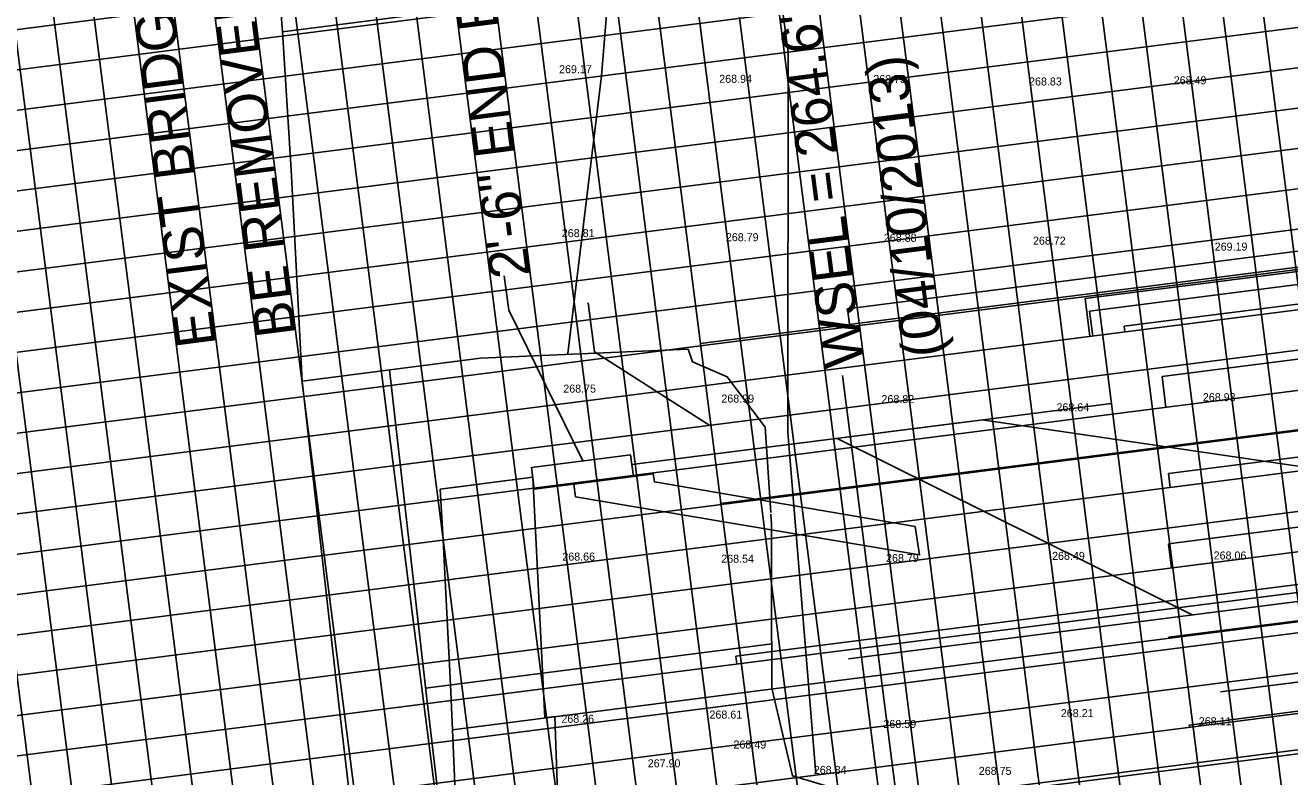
# Model space of a CAD drawing. Extents: x 2166991 to 2168450, y 842134 to 844444.
# Drawn here: x 2167712.5 to 2167870.5, y 843413.8 to 843507.6 of the extents above; entities that cross this region are included whole.
import ezdxf

# ---------------------------------------------------------------- set-up
doc = ezdxf.new("R2010")
doc.units = 0
for name, color, linetype in [('Exist Hydrographic Top of Bank', 7, 'Continuous'), ('Exist Plan Preparation Drainage Notes Label', 7, 'Continuous'), ('Prop Boundary Buffer Zone 1', 7, 'Continuous'), ('Prop Boundary Buffer Zone 2', 7, 'Continuous'), ('Prop Drainage Structure Bridge', 7, 'Continuous'), ('Prop Drainage Structure Drop Inlet Grate 2 Narrow Slots and Flat Grates 840 29 CELL', 7, 'Continuous'), ('Prop Drainage Structure Drop Inlet Grate 2 Wide Slots and Flat Grates 840 20 TB Label', 7, 'Continuous'), ('Prop Drainage Structure Pipe Collar Label', 7, 'Continuous'), ('Prop Drainage Structure Pipe CSP 18in Label', 7, 'Continuous'), ('Prop Drainage Structure Scour Hole CELL', 7, 'Continuous'), ('Prop Drainage Structure Scour Hole Label', 7, 'Continuous'), ('Prop Erosion Rip Rap Class II', 7, 'Continuous'), ('Prop Plan Preparation Excavation Hatching', 7, 'Continuous'), ('Prop Plan Preparation Excavation Hatching Label', 7, 'Continuous'), ('Scratch_Level_1', 7, 'Continuous'), ('Scratch_Level_3', 7, 'Continuous')]:
    doc.layers.add(name, color=color, linetype=linetype)

msp = doc.modelspace()

# ---------------------------------------------------------------- linework, layer by layer
at = {"layer": 'Exist Hydrographic Top of Bank'}
msp.add_lwpolyline([(2167772.38, 843476.34), (2167772.93, 843472.04), (2167782.2, 843453.23)], dxfattribs=at)
at = {"layer": 'Exist Plan Preparation Drainage Notes Label'}
for p, q in [((2167933.95, 842789.5), (2167775.57, 844029.42)), ((2167884.35, 842783.16), (2167725.98, 844023.09)), ((2167834.76, 842776.83), (2167676.38, 844016.75)), ((2167950.62, 842816.83), (2167798.58, 844007.16)), ((2167955.58, 842817.46), (2167803.54, 844007.79)), ((2167940.7, 842815.56), (2167788.66, 844005.89)), ((2167945.66, 842816.2), (2167793.62, 844006.52)), ((2167925.82, 842813.66), (2167773.78, 844003.99)), ((2167935.74, 842814.93), (2167783.7, 844005.26)), ((2167915.9, 842812.39), (2167763.86, 844002.72)), ((2167920.86, 842813.03), (2167768.82, 844003.36)), ((2167901.03, 842810.49), (2167748.98, 844000.82)), ((2167905.98, 842811.13), (2167753.94, 844001.46)), ((2167910.94, 842811.76), (2167758.9, 844002.09)), ((2167891.11, 842809.23), (2167739.06, 843999.56)), ((2167896.07, 842809.86), (2167744.02, 844000.19)), ((2167876.23, 842807.33), (2167724.19, 843997.66)), ((2167886.15, 842808.59), (2167734.11, 843998.92)), ((2167866.31, 842806.06), (2167714.27, 843996.39)), ((2167871.27, 842806.69), (2167719.23, 843997.02)), ((2167851.43, 842804.16), (2167699.39, 843994.49)), ((2167856.39, 842804.79), (2167704.35, 843995.12)), ((2167861.35, 842805.43), (2167709.31, 843995.76)), ((2167841.51, 842802.89), (2167689.47, 843993.22)), ((2167846.47, 842803.53), (2167694.43, 843993.85)), ((2167826.63, 842800.99), (2167674.59, 843991.32)), ((2167836.55, 842802.26), (2167684.51, 843992.59)), ((2167816.71, 842799.72), (2167664.67, 843990.05)), ((2167821.67, 842800.36), (2167669.63, 843990.69)), ((2167801.83, 842797.82), (2167649.79, 843988.15)), ((2167806.79, 842798.46), (2167654.75, 843988.79)), ((2167811.75, 842799.09), (2167659.71, 843989.42)), ((2167791.91, 842796.56), (2167639.87, 843986.89)), ((2167796.87, 842797.19), (2167644.83, 843987.52)), ((2168137.77, 843561.54), (2167641.8, 843498.19)), ((2168138.41, 843556.58), (2167642.44, 843493.23)), ((2168139.04, 843551.62), (2167643.07, 843488.27)), ((2168139.68, 843546.66), (2167618.91, 843480.15)), ((2168140.31, 843541.7), (2167644.34, 843478.35)), ((2168140.94, 843536.74), (2167644.97, 843473.39)), ((2168141.58, 843531.78), (2167645.61, 843468.43)), ((2168142.21, 843526.83), (2167646.24, 843463.47)), ((2168142.84, 843521.87), (2167646.87, 843458.52)), ((2168143.48, 843516.91), (2167647.51, 843453.56)), ((2168144.11, 843511.95), (2167648.14, 843448.6)), ((2168144.74, 843506.99), (2167648.77, 843443.64)), ((2168145.38, 843502.03), (2167649.41, 843438.68)), ((2168146.01, 843497.07), (2167625.24, 843430.55)), ((2168146.64, 843492.11), (2167650.67, 843428.76)), ((2168147.28, 843487.15), (2167651.31, 843423.8)), ((2168147.91, 843482.19), (2167651.94, 843418.84)), ((2168148.54, 843477.23), (2167652.57, 843413.88)), ((2168149.18, 843472.27), (2167653.21, 843408.92)), ((2168149.81, 843467.31), (2167653.84, 843403.96)), ((2168150.44, 843462.35), (2167654.47, 843399)), ((2168151.08, 843457.39), (2167655.11, 843394.04)), ((2168151.71, 843452.43), (2167655.74, 843389.08))]:
    msp.add_line(p, q, dxfattribs=at)
at = {"layer": 'Prop Boundary Buffer Zone 1'}
for p, q in [((2168091.54, 843505.51), (2167796.91, 843467.87)), ((2168090.16, 843485.03), (2167799.4, 843447.89)), ((2167796.94, 843467.6), (2167796.91, 843467.87)), ((2168089.2, 843465.59), (2167801.33, 843428.82)), ((2167799.41, 843447.76), (2167799.4, 843447.89)), ((2168087.87, 843444.75), (2167804.17, 843408.52)), ((2167801.45, 843427.85), (2167801.33, 843428.82))]:
    msp.add_line(p, q, dxfattribs=at)
at = {"layer": 'Prop Boundary Buffer Zone 2'}
for p, q in [((2167747.12, 843463.2), (2167769.41, 843466.04)), ((2167762.53, 843424.84), (2167805.8, 843430.37))]:
    msp.add_line(p, q, dxfattribs=at)
for points in [[(2167771.47, 843345.33), (2167771.01, 843349.66), (2167769.81, 843363.4), (2167767.4, 843383.52), (2167762.64, 843423.88), (2167758.03, 843464.59)], [(2167760.56, 843343.94), (2167760.1, 843348.27), (2167758.9, 843362.01), (2167756.48, 843382.13), (2167751.73, 843422.48), (2167747.12, 843463.2)]]:
    msp.add_lwpolyline(points, dxfattribs=at)
at = {"layer": 'Prop Drainage Structure Bridge'}
msp.add_line((2167795.37, 843467.16), (2167769.41, 843466.04), dxfattribs=at)
for points in [[(2167805.68, 843446.76), (2167804.98, 843457.45), (2167800.25, 843463.71), (2167795.92, 843465.61), (2167795.37, 843467.16)], [(2167821.21, 843410.07), (2167808.38, 843413.88), (2167805.82, 843424.85), (2167805.79, 843436.55), (2167805.78, 843445.31), (2167805.69, 843446.57)]]:
    msp.add_lwpolyline(points, dxfattribs=at)
at = {"layer": 'Prop Drainage Structure Drop Inlet Grate 2 Narrow Slots and Flat Grates 840 29 CELL'}
msp.add_lwpolyline([(2167811.3, 843414.12), (2167807.83, 843456.76), (2167807.84, 843504.28), (2167801.18, 843553.83), (2167790.23, 843580.86), (2167790.98, 843602.94), (2167784.08, 843652.46), (2167781.01, 843702.48), (2167748.47, 843748.73), (2167729.16, 843847.07), (2167716.86, 843895.91), (2167712.99, 843945.82), (2167712.65, 843970.98), (2167709.18, 843995.74)], dxfattribs=at)
at = {"layer": 'Prop Drainage Structure Drop Inlet Grate 2 Wide Slots and Flat Grates 840 20 TB Label'}
msp.add_lwpolyline([(2167781.08, 843450.32), (2167781.28, 843448.75), (2167824.28, 843441.49), (2167823.72, 843445.01), (2167791.15, 843450.59), (2167790.99, 843451.61), (2167788.51, 843451.29)], close=True, dxfattribs=at)
at = {"layer": 'Prop Drainage Structure Pipe Collar Label'}
msp.add_line((2167942.23, 843442.17), (2167832.09, 843458.36), dxfattribs=at)
at = {"layer": 'Prop Drainage Structure Pipe CSP 18in Label'}
for p, q in [((2167794.54, 843453.55), (2167848.25, 843460.41)), ((2167788.33, 843452.77), (2167829.5, 843458.03)), ((2167775.78, 843452.41), (2167788.18, 843454)), ((2167788.17, 843454), (2167788.52, 843451.28)), ((2167764.37, 843449.7), (2167775.94, 843451.17)), ((2167766.02, 843449.91), (2167775.94, 843451.17)), ((2167776.13, 843449.69), (2167788.53, 843451.27)), ((2167765.91, 843419.65), (2167942.23, 843442.17))]:
    msp.add_line(p, q, dxfattribs=at)
for points in [[(2167780.51, 843320.7), (2167779.93, 843350.87), (2167781.17, 843351.03), (2167778.7, 843421.28), (2167777.46, 843421.13), (2167775.94, 843451.17)], [(2167768.96, 843319.23), (2167768.73, 843332.94), (2167768.63, 843337.97), (2167768.48, 843344.95), (2167768.38, 843349.4), (2167768.21, 843356.31), (2167767.95, 843365.56), (2167767.37, 843383.75), (2167767.32, 843385.13), (2167766.83, 843398.23), (2167765.91, 843419.65), (2167765.64, 843425.24), (2167764.98, 843438.32), (2167764.72, 843443.32), (2167764.37, 843449.7)]]:
    msp.add_lwpolyline(points, dxfattribs=at)
at = {"layer": 'Prop Drainage Structure Scour Hole CELL'}
msp.add_line((2167776.13, 843449.7), (2167775.78, 843452.43), dxfattribs=at)
at = {"layer": 'Prop Drainage Structure Scour Hole Label'}
for p, q in [((2168088.64, 843507.14), (2167815.29, 843472.22)), ((2168088.67, 843504.62), (2167844.97, 843473.49)), ((2168088.99, 843503.04), (2167845.52, 843471.94)), ((2168088.56, 843500.54), (2167849.85, 843470.04)), ((2168087.31, 843493.51), (2167854.58, 843463.78)), ((2168086.48, 843481.16), (2167855.37, 843451.64)), ((2167845.57, 843468.77), (2167844.97, 843473.49)), ((2167815.58, 843469.98), (2167815.29, 843472.22)), ((2167845.92, 843468.82), (2167845.52, 843471.94)), ((2168085.73, 843472.3), (2167855.38, 843442.88)), ((2167849.94, 843469.33), (2167849.85, 843470.04)), ((2167855.07, 843459.91), (2167854.58, 843463.78)), ((2168086.66, 843460.73), (2167855.42, 843431.19)), ((2167855.6, 843449.89), (2167855.37, 843451.64)), ((2168086.56, 843449.42), (2167857.98, 843420.22)), ((2167855.77, 843439.83), (2167855.38, 843442.88)), ((2167855.43, 843431.08), (2167855.42, 843431.19)), ((2167858.01, 843419.96), (2167857.98, 843420.22))]:
    msp.add_line(p, q, dxfattribs=at)
at = {"layer": 'Prop Erosion Rip Rap Class II'}
for points in [[(2167798.06, 843457.66), (2167783.65, 843466.84), (2167782.87, 843472.96)], [(2167814.63, 843463.88), (2167822.41, 843403.37), (2167826.31, 843403.86)]]:
    msp.add_lwpolyline(points, dxfattribs=at)
at = {"layer": 'Prop Plan Preparation Excavation Hatching'}
msp.add_lwpolyline([(2167780.31, 843466.62), (2167784.52, 843501.3), (2167788.71, 843552.24), (2167783.57, 843580.01), (2167779.35, 843601.45), (2167769.15, 843650.56), (2167754.8, 843699.13), (2167753.25, 843749.34), (2167741.46, 843798.24), (2167722.31, 843846.2), (2167712.49, 843895.35), (2167692.49, 843943.2), (2167687.3, 843967.74), (2167682.51, 843992.33)], dxfattribs=at)
at = {"layer": 'Prop Plan Preparation Excavation Hatching Label'}
msp.add_lwpolyline([(2167698.15, 843912.6), (2167700.9, 843897.02), (2167704.98, 843873.76), (2167712.78, 843830.82), (2167715.25, 843815.08), (2167719.44, 843788.58), (2167721.24, 843770.88), (2167724.14, 843742.72), (2167725.44, 843727.75), (2167727.98, 843698.45), (2167729.76, 843678.17), (2167732.36, 843648.31), (2167734.01, 843631.06), (2167736.91, 843601.24), (2167740.82, 843556.48), (2167742.38, 843536.39), (2167744.64, 843506.82), (2167745.73, 843489.59), (2167747.12, 843463.2)], dxfattribs=at)
at = {"layer": 'Scratch_Level_1'}
for p in [(2168101.65, 843552.42), (2167744.71, 843506.3)]:
    msp.add_line(p, (2167744.64, 843506.82), dxfattribs=at)
at = {"layer": 'Scratch_Level_3'}
for p, q in [((2167815.39, 843428.51), (2168411.81, 843504.69)), ((2167861.89, 843424.37), (2168413.08, 843494.78)), ((2167858.33, 843434), (2167813.96, 843456.03))]:
    msp.add_line(p, q, dxfattribs=at)

# ---------------------------------------------------------------- texts
at = {"layer": 'Exist Hydrographic Top of Bank'}
msp.add_text('2\'-6" END BENT CAPS', height=5, rotation=97.279, dxfattribs=at).set_placement((2167775.63, 843476.4))
at = {"layer": 'Prop Erosion Rip Rap Class II'}
for s, p in [('EXIST BRIDGE TO', (2167736.43, 843467.74)), ('BE REMOVED', (2167746.35, 843469.01)), ("WSEL = 264.6'", (2167817.32, 843465.21)), ('(04/10/2013)', (2167827.24, 843466.48))]:
    msp.add_text(s, height=5, rotation=97.279, dxfattribs=at).set_placement(p)
at = {"layer": 'Scratch_Level_3'}
for s, p in [('269.17', (2167779.22, 843501.64)), ('268.94', (2167799.24, 843500.44)), ('268.73', (2167818.49, 843500.42)), ('268.83', (2167837.96, 843500.11)), ('268.49', (2167856.04, 843500.25)), ('268.81', (2167779.57, 843481.17)), ('268.79', (2167800.07, 843480.66)), ('268.88', (2167819.81, 843480.59)), ('268.72', (2167838.45, 843480.23)), ('269.19', (2167861.16, 843479.48)), ('268.75', (2167779.75, 843461.75)), ('268.99', (2167799.51, 843460.51)), ('268.82', (2167819.52, 843460.44)), ('268.64', (2167841.39, 843459.42)), ('268.93', (2167859.68, 843460.68)), ('268.66', (2167779.63, 843440.77)), ('268.54', (2167799.49, 843440.51)), ('268.79', (2167820.09, 843440.59)), ('268.49', (2167840.84, 843440.86)), ('268.06', (2167861.03, 843440.91)), ('268.26', (2167779.51, 843420.51)), ('268.61', (2167798.02, 843421.04)), ('268.59', (2167819.76, 843419.87)), ('268.21', (2167841.93, 843421.22)), ('268.11', (2167859.17, 843420.21)), ('268.49', (2167801.02, 843417.3)), ('267.90', (2167790.3, 843414.95)), ('268.84', (2167811.06, 843414.13)), ('268.75', (2167831.68, 843414.01))]:
    msp.add_text(s, height=1, dxfattribs=at).set_placement(p)

doc.saveas('drawing.dxf')
